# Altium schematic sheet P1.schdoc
size 297 x 209 mm; Symbol: Drawing-Symbol_A4; @Project Name: MyMidiKeyboard; @Page Count: 1; @Update Date: 2026-10-24; @Create Date: 2026-10-24; @Schematic Name: Schematic1; @Page No: 1; @Page Name: P1; Company: EasyEDA.com; Version: V1.0; Page Size: A4; Device: Drawing-Symbol_A4; @Create Time: 17:01:59; @Update Time: 17:01:59; Border: 1; Width: 1170; Height: 825; Region Start: 1; X Region Count: 6; Y Region Count: 4; Blade Width: 10; Title Block Position: 3; @Board Name: Board1
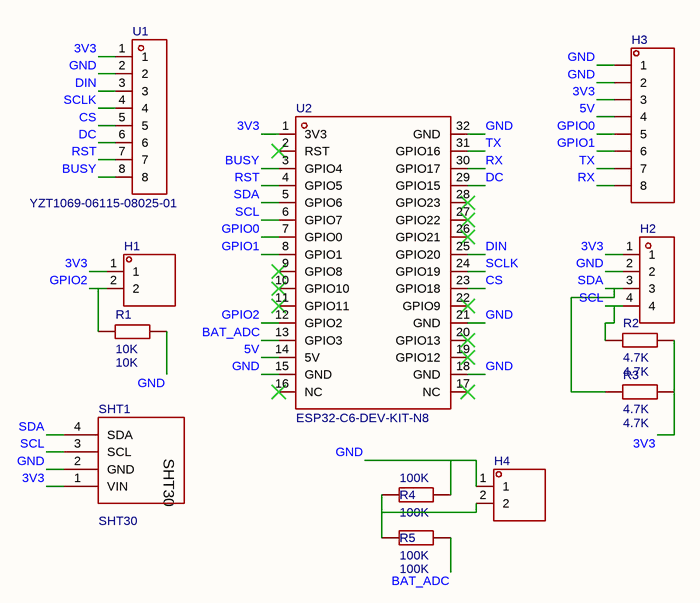
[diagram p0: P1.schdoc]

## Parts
H1  (no value)  [HDR-TH_2P-P2.54-V-M-1]
H2  (no value)  [HDR-TH_4P-P2.54-V-M]
H3  (no value)  [HDR-TH_8P-P2.54-V-M]
H4  (no value)  [HDR-TH_2P-P2.54-V-M-1]
R1  10K  [R0603]
R2  4.7K  [R0603]
R3  4.7K  [R0603]
R4  100K  [R0603]
R5  100K  [R0603]
SHT1  SHT30  [SHT30]
U1  YZT1069-06115-08025-01  [HDR-TH_8P-P2.54-V-M]
U2  ESP32-C6-DEV-KIT-N8  [COMM-SMD_L55.0-W25.4_ESP32-C6-DEV-KIT-N8]

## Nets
3V3: H1.1 H2.1 H3.3 R2.2 R3.2 SHT1.1(VIN) U1.1 U2.1(3V3)
5V: H3.4 U2.14(5V)
BAT_ADC: R5.2 U2.13(GPIO3)
BUSY: U1.8 U2.3(GPIO4)
CS: U1.5 U2.23(GPIO18)
DC: U1.6 U2.29(GPIO15)
DIN: U1.3 U2.25(GPIO20)
GND: H2.2 H3.1 H3.2 H4.1 R1.2 R4.2 SHT1.2(GND) U1.2 U2.15(GND) U2.18(GND) U2.21(GND) U2.32(GND)
GPIO0: H3.5 U2.7(GPIO0)
GPIO1: H3.6 U2.8(GPIO1)
GPIO2: H1.2 R1.1 U2.12(GPIO2)
RST: U1.7 U2.4(GPIO5)
RX: H3.8 U2.30(GPIO17)
SCL: H2.4 R2.1 SHT1.3(SCL) U2.6(GPIO7)
SCLK: U1.4 U2.24(GPIO19)
SDA: H2.3 R3.1 SHT1.4(SDA) U2.5(GPIO6)
TX: H3.7 U2.31(GPIO16)
NetH4_2: H4.2 R4.1 R5.1

Not connected (* = marked no-connect by the designer): U2 2(RST)* 9(GPIO8)* 10(GPIO10)* 11(GPIO11)* 16(NC)* 17(NC)* 19(GPIO12)* 20(GPIO13)* 22(GPIO9)* 26(GPIO21)* 27(GPIO22)* 28(GPIO23)*

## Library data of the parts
H1 = HDR-M_2.54_1x2P: Symbol: 210S-1*2P L=11.6MMGold-plated black; ConvertToPcb: yes; ModelId: e506c2b6a89c4aacb020357246aab7250819f05c4eef4c71ace90d822a990e87; ModelName: HDR-M-2.54_1x2; ModelTransform: 200,100,0,0,0,0,0,0,-118.11
H2 = HDR-M_2.54_1x4P: Symbol: PZ254V-11-04P; ConvertToPcb: yes; ModelId: 69e0934d9b9245f6ab499bc5a319b3aa0819f05c4eef4c71ace90d822a990e87; ModelName: HDR-TH_4P-P2.54-M-LI-1X4P; ModelTransform: 399.999,104.7242,0,0,0,0,0,0,-118.11
H3 = HDR-M_2.54_1x8P: Symbol: Header-Male-2.54_1x8; ConvertToPcb: yes; ModelId: 926dcf5c05be473f8295f20cc8ccf72f0819f05c4eef4c71ace90d822a990e87; ModelTransform: 807.87244,98.425,0,0,0,0,0,0,-118.11
H4 = HDR-M_2.54_1x2P: Symbol: 210S-1*2P L=11.6MMGold-plated black; 3D Model: e506c2b6a89c4aacb020357246aab7250819f05c4eef4c71ace90d822a990e87; 3D Model Transform: 200,100,0,0,0,0,0,0,-118.11; ConvertToPcb: yes; ModelName: HDR-M-2.54_1x2
R1-R3 = Res_0603: Symbol: Res; ConvertToPcb: yes; ModelId: 112863783b5b41f1b5254f87eedc79320819f05c4eef4c71ace90d822a990e87; ModelTransform: 31.8897,63.7794,0,90,0,0,0,0,0
R4 R5 = Res_0603: Symbol: Res; 3D Model: 112863783b5b41f1b5254f87eedc79320819f05c4eef4c71ace90d822a990e87; 3D Model Transform: 31.8897,63.7794,0,90,0,0,0,0,0; ConvertToPcb: yes
SHT1 = SHT30: ConvertToPcb: yes
U1 = YZT1069-06115-08025-01: Pin Structure:1x8P Pitch:2.54mm Circluar Pins/Square Pins:Pin Header Mounting Type:Through Hole Number of Rows:1 Number of Pins:8P Current Rating:3A Length of Mating Pin:6mm Insulation Height:2.54mm Length of End Connection Pin:3mm Contact Material:Copper; Manufacturer: Xinyangze(鑫扬泽); AddInBom: yes; ModelId: 926dcf5c05be473f8295f20cc8ccf72f0819f05c4eef4c71ace90d822a990e87; ModelTransform: 807.87244,98.425,0,0,0,0,0,0,-118.11; Pin Structure: 1x8P; Pitch: 2.54mm; Current Rating: 3A
U2 = ESP32-C6-DEV-KIT-N8: AddInBom: yes; ModelId: 981d4a97818c48e7917fc2dd6da416b40819f05c4eef4c71ace90d822a990e87; ModelTransform: 998.42312,2169.287,0,0,0,0,0.003,-139.763,0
